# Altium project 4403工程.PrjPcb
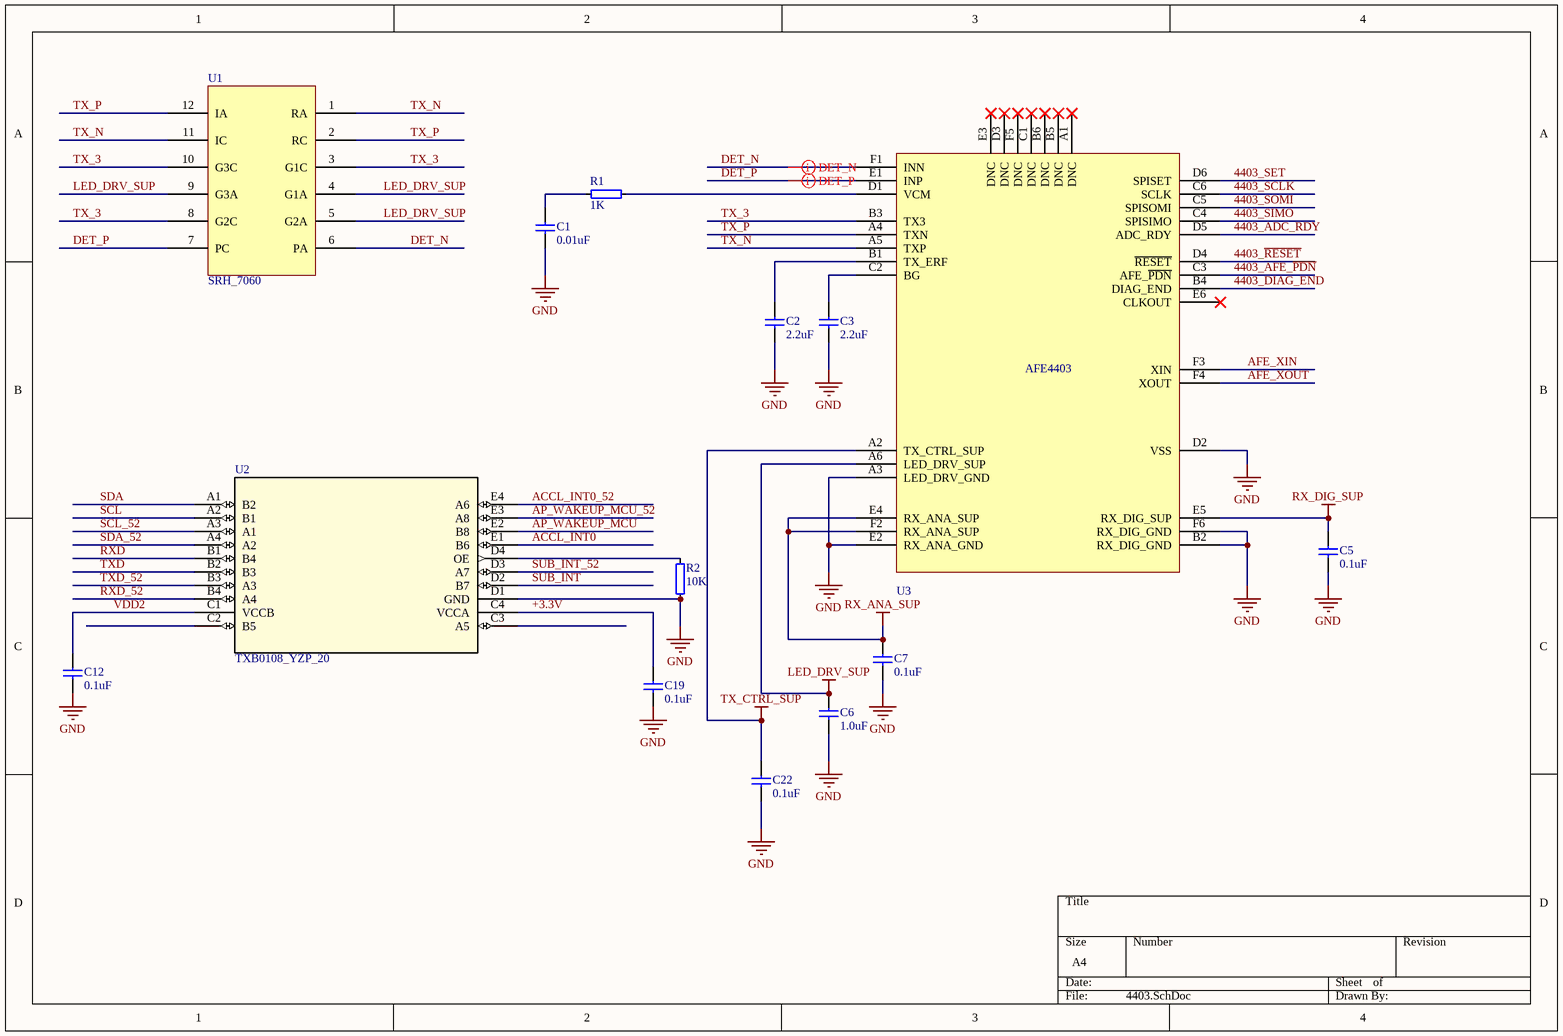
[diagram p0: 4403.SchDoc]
3 sheets, 38 parts. Net scope: global (net labels, ports and power ports of the same name join across sheets).
Board file: 4403_PCB.PcbDoc
Sheets:
  4403.SchDoc
  pca10040_sheet1_radio.SchDoc
  POWER.SchDoc

## Sheet 4403.SchDoc
size A4

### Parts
C1  0.01uF  [0201]
C2  2.2uF  [0402]
C3  2.2uF  [0402]
C5  0.1uF  [0201]
C6  1.0uF  [0402]
C7  0.1uF  [0201]
C12  0.1uF  [0201]
C19  0.1uF  [0201]
C22  0.1uF  [0201]
R1  1K  [0201]
R2  10K  [0201]
U1  SRH_7060  [SRH_7060]
U2  TXB0108_YZP_20  [BGA20C50P4X5_189X239X50]
U3  AFE4403  [BGA36C50P6X6_304X304X50]

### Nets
+3.3V: C5.2 C7.2 C19.2 U2.C4(VCCA) U3.E4(RX_ANA_SUP) U3.E5(RX_DIG_SUP) U3.F2(RX_ANA_SUP)  [also labelled RX_ANA_SUP, RX_DIG_SUP]
GND: C1.1 C2.1 C3.1 C5.1 C6.1 C7.1 C12.1 C19.1 C22.1 R2.1 U2.D1(GND) U3.A3(LED_DRV_GND) U3.B2(RX_DIG_GND) U3.D2(VSS) U3.E2(RX_ANA_GND) U3.F6(RX_DIG_GND)
LED_DRV_SUP: C6.2 C22.2 U1.4(G1A) U1.5(G2A) U1.9(G3A) U3.A2(TX_CTRL_SUP) U3.A6(LED_DRV_SUP)  [also labelled TX_CTRL_SUP]
4403_ADC_RDY: U3.D5(ADC_RDY)
4403_AFE_~{PDN}: U3.C3(AFE_~{PDN})
4403_DIAG_END: U3.B4(DIAG_END)
4403_~{RESET}: U3.D4(~{RESET})
4403_SCLK: U3.C6(SCLK)
4403_SET: U3.D6(SPISET)
4403_SIMO: U3.C4(SPISIMO)
4403_SOMI: U3.C5(SPISOMI)
ACCL_INT0: U2.E1(B6)
ACCL_INT0_52: U2.E4(A6)
AFE_XIN: U3.F3(XIN)
AFE_XOUT: U3.F4(XOUT)
AP_WAKEUP_MCU: U2.E2(B8)
AP_WAKEUP_MCU_52: U2.E3(A8)
DET_N: U1.6(PA) U3.F1(INN)
DET_P: U1.7(PC) U3.E1(INP)
RXD: U2.B1(B4)
RXD_52: U2.B4(A4)
SCL: U2.A2(B1)
SCL_52: U2.A3(A1)
SDA: U2.A1(B2)
SDA_52: U2.A4(A2)
SUB_INT: U2.D2(B7)
SUB_INT_52: U2.D3(A7)
TX_3: U1.3(G1C) U1.8(G2C) U1.10(G3C) U3.B3(TX3)
TX_N: U1.1(RA) U1.11(IC) U3.A5(TXP)
TX_P: U1.2(RC) U1.12(IA) U3.A4(TXN)
TXD: U2.B2(B3)
TXD_52: U2.B3(A3)
VDD2: C12.2 U2.C1(VCCB)
NetC1_2: C1.2 R1.1
NetC2_2: C2.2 U3.B1(TX_ERF)
NetC3_2: C3.2 U3.C2(BG)
NetR1_2: R1.2 U3.D1(VCM)
NetR2_2: R2.2 U2.D4(OE)

Not connected (* = marked no-connect by the designer): U2 C2(B5) C3(A5); U3 A1(DNC)* B5(DNC)* B6(DNC)* C1(DNC)* D3(DNC)* E3(DNC)* E6(CLKOUT)* F5(DNC)*

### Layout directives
differential pair: DET_N, DET_P

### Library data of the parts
C1 C5 C7 C12 C19 C22 = CAP_0201: Capacitor, NP0, ±0.1pF; Part Number: C0201-1.2p; Note: 50V; Artikkelnr Noca: 20029157; Artikkelnr Simpro: N.A.
C2 C3 C6 = CAP_0402: Capacitor, NP0, ±0.1pF; Part Number: C0402-1.2p; Note: 50V; Artikkelnr Noca: 20029157; Artikkelnr Simpro: N.A.
R1 R2 = RES_0201: Not mounted; Part Number: R0201-N.C.; Note: Chip Res; Artikkelnr Noca: N.A.
U2 = TXB0108_YZP_20: Imported; Vendor: Texas Instruments; PACKAGE_DESIGNATOR: YZP; PIN_COUNT: 20; FAMILY_NAME: AUTO DIRECTION SENSING DUAL SUPPLY TRANSLATOR; INDUSTRY_STD_PKG_TYPE: DSBGA

## Sheet pca10040_sheet1_radio.SchDoc: PCA10040 - nRF Radio
size A4; Revision: 1.1.0; SheetNumber: 1; SheetTotal: 5; DrawnBy: KJP; ProjectNumber: 4397; PCBRevision: 0071KJP; DocumentSize: A4; PCAName: PCA10040; PCBNumber: 400150
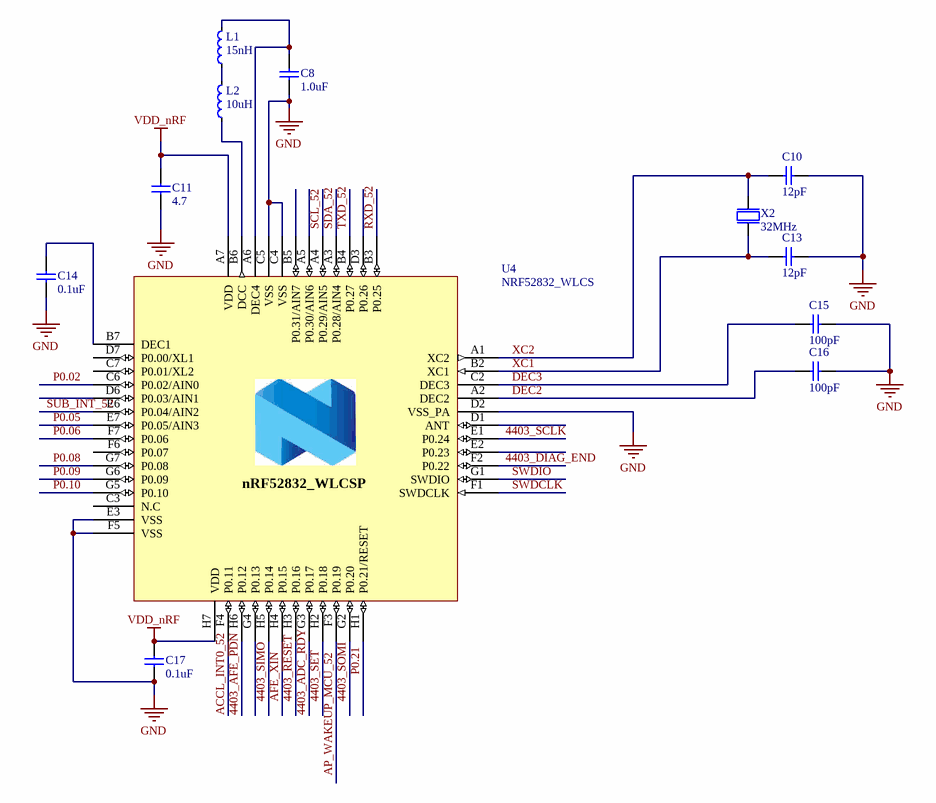
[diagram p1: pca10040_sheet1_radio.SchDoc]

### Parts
C8  1.0uF  [0402]
C10  12pF  [0201]
C11  4.7  [0603]
C13  12pF  [0201]
C14  0.1uF  [0201]
C15  100pF  [0201]
C16  100pF  [0201]
C17  0.1uF  [0201]
L1  15nH  [INDC1608X06L]
L2  10uH  [INDC1608X06L]
U4  NRF52832_WLCS  [BGA56C40P7X8_300X320X38]
X2  32MHz  [BT-XTAL_2016]

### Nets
GND: C8.1 C10.1 C11.1 C13.1 C14.1 C15.1 C16.1 C17.1 U4.C4(VSS) U4.C5(VSS) U4.D2(VSS_PA) U4.E3(VSS) U4.F5(VSS) X2.2(GND) X2.4(GND)
VDD_nRF: C11.2 C17.2 U4.A7(VDD) U4.H7(VDD)  [project net +3.3V]
4403_ADC_RDY: U4.G3(P0.17)
4403_AFE_~{PDN}: U4.H6(P0.12)
4403_DIAG_END: U4.F2(P0.22)
4403_~{RESET}: U4.H3(P0.16)
4403_SCLK: U4.E1(P0.24)
4403_SET: U4.H2(P0.18)
4403_SIMO: U4.H5(P0.14)
4403_SOMI: U4.G2(P0.20)
ACCL_INT0_52: U4.F4(P0.11)
AFE_XIN: U4.H4(P0.15)
AP_WAKEUP_MCU_52: U4.F3(P0.19)
DEC2: C16.2 U4.A2(DEC2)
DEC3: C15.2 U4.C2(DEC3)
P0.02: U4.C6(P0.02/AIN0)
P0.05: U4.E7(P0.05/AIN3)
P0.06: U4.F7(P0.06)
P0.08: U4.G7(P0.08)
P0.09: U4.G6(P0.09)
P0.10: U4.G5(P0.10)
P0.21: U4.H1(P0.21/RESET)
RXD_52: U4.B3(P0.25)
SCL_52: U4.A4(P0.29/AIN5)
SDA_52: U4.A3(P0.28/AIN4)
SUB_INT_52: U4.E6(P0.04/AIN2)
SWDCLK: U4.F1(SWDCLK)
SWDIO: U4.G1(SWDIO)
TXD_52: U4.B4(P0.27)
XC1: C13.2 U4.B2(XC1) X2.1(inp)
XC2: C10.2 U4.A1(XC2) X2.3(out)
NetC8_2: C8.2 L1.2 U4.A6(DEC4)
NetC14_2: C14.2 U4.B7(DEC1)
NetL1_1: L1.1 L2.2
NetL2_1: L2.1 U4.B6(DCC)

Not connected (* = marked no-connect by the designer): U4 A5(P0.30/AIN6) B5(P0.31/AIN7) C3(N.C) C7(P0.01/XL2) D1(ANT) D3(P0.26) D6(P0.03/AIN1) D7(P0.00/XL1) E2(P0.23) F6(P0.07) G4(P0.13)

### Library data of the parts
C8 = CAP_0402: as C2 on sheet 4403
C10 C13-C17 = CAP_0201: as C1 on sheet 4403
C11 = CAP_0603: Capacitor, NP0, ±0.1pF; Part Number: C0603-1.2p; Note: 50V; Artikkelnr Noca: 20029157; Artikkelnr Simpro: N.A.
L1 L2 = IND_0603: Inductor, 80mA, ±10%; Part Number: L0603-10µ; Manufacturer: Taiyo Yuden; Manufacturer Part Number: LBMF1608T100K; 2nd source part number: 178-6105; Note: LBMF1608T100K 10µH 80mA 0603; Artikkelnr Noca: 33029314; Artikkelnr Simpro: N.A.
U4 = NRF52832_WLCSP
X2 = XTAL_SMD2016: XTAL SMD 2016, 32MHz, Cl=8pF, Tol: ±10ppm, Stab: ±10ppm; Part Number: XTAL_SMD2016_32MHz_8pF_Epson; Manufacturer: Epson Toyocom; Manufacturer Part Number: Q22FA12800025; Note: XTAL SMD 32.000MHz; Artikkelnr Noca: N.A.

## Sheet POWER.SchDoc
size A4
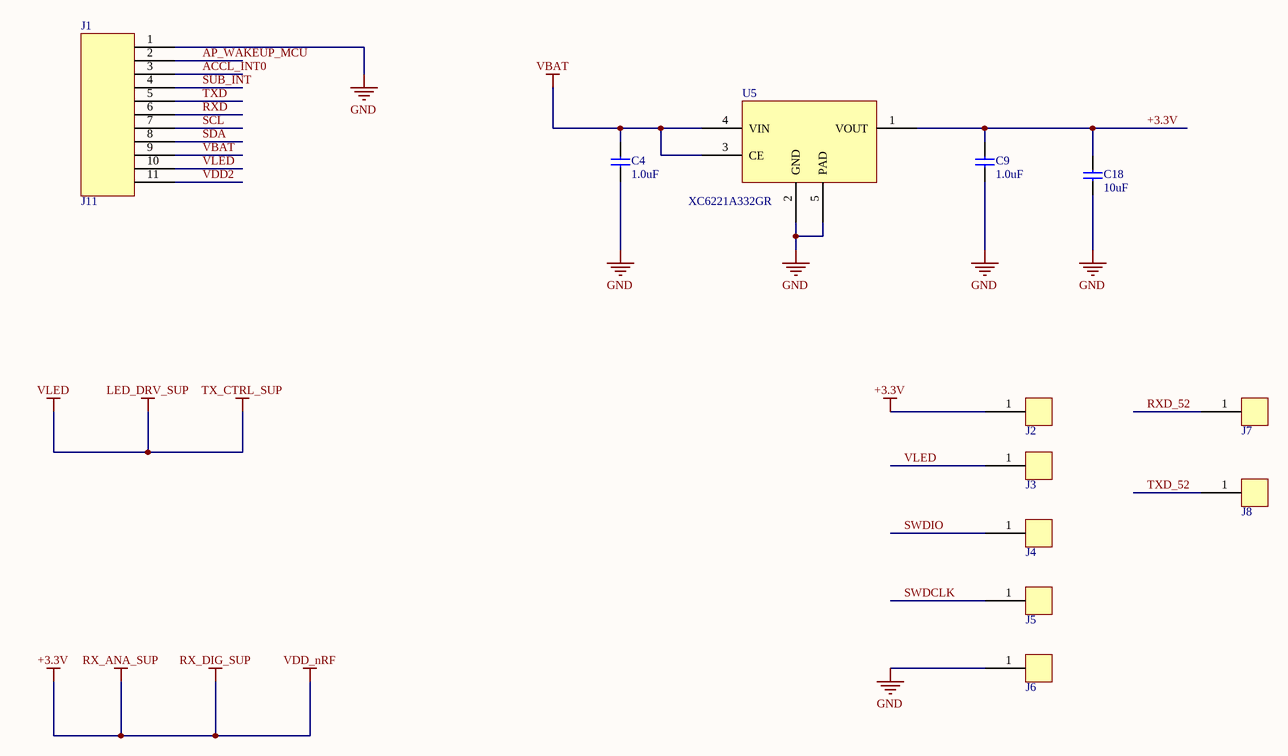
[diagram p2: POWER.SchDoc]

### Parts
C4  1.0uF  [0402]
C9  1.0uF  [0402]
C18  10uF  [0603]
J1  J11  [J11]
J2  PAD  [PAD1.5]  (value not drawn)
J3  PAD  [PAD1.5]  (value not drawn)
J4  PAD  [PAD1.5]  (value not drawn)
J5  PAD  [PAD1.5]  (value not drawn)
J6  PAD  [PAD1.5]  (value not drawn)
J7  PAD  [PAD1.5]  (value not drawn)
J8  PAD  [PAD1.5]  (value not drawn)
U5  XC6221A332GR  [USP-4]

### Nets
+3.3V: C9.2 C18.2 J2.1(PAD) U5.1(VOUT)  [also labelled RX_ANA_SUP, RX_DIG_SUP, VDD_nRF]
GND: C4.1 C9.1 C18.1 J1.1 J6.1(PAD) U5.2(GND) U5.5(PAD)
LED_DRV_SUP: J1.10 J3.1(PAD)  [also labelled TX_CTRL_SUP, VLED]
VBAT: C4.2 J1.9 U5.3(CE) U5.4(VIN)
ACCL_INT0: J1.3
AP_WAKEUP_MCU: J1.2
RXD: J1.6
RXD_52: J7.1(PAD)
SCL: J1.7
SDA: J1.8
SUB_INT: J1.4
SWDCLK: J5.1(PAD)
SWDIO: J4.1(PAD)
TXD: J1.5
TXD_52: J8.1(PAD)
VDD2: J1.11

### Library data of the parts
C4 C9 = CAP_0402: as C2 on sheet 4403
C18 = CAP_0603: as C11 on sheet pca10040_sheet1_radio

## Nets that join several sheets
+3.3V: 4403 (7 pins), pca10040_sheet1_radio (C11.2 C17.2 U4.A7 U4.H7), POWER (C9.2 C18.2 J2.1 U5.1)
GND: 4403 (16 pins), pca10040_sheet1_radio (15 pins), POWER (7 pins)
LED_DRV_SUP: 4403 (7 pins), POWER (J1.10 J3.1)
4403_ADC_RDY: 4403 (U3.D5), pca10040_sheet1_radio (U4.G3)
4403_AFE_~{PDN}: 4403 (U3.C3), pca10040_sheet1_radio (U4.H6)
4403_DIAG_END: 4403 (U3.B4), pca10040_sheet1_radio (U4.F2)
4403_~{RESET}: 4403 (U3.D4), pca10040_sheet1_radio (U4.H3)
4403_SCLK: 4403 (U3.C6), pca10040_sheet1_radio (U4.E1)
4403_SET: 4403 (U3.D6), pca10040_sheet1_radio (U4.H2)
4403_SIMO: 4403 (U3.C4), pca10040_sheet1_radio (U4.H5)
4403_SOMI: 4403 (U3.C5), pca10040_sheet1_radio (U4.G2)
ACCL_INT0: 4403 (U2.E1), POWER (J1.3)
ACCL_INT0_52: 4403 (U2.E4), pca10040_sheet1_radio (U4.F4)
AFE_XIN: 4403 (U3.F3), pca10040_sheet1_radio (U4.H4)
AP_WAKEUP_MCU: 4403 (U2.E2), POWER (J1.2)
AP_WAKEUP_MCU_52: 4403 (U2.E3), pca10040_sheet1_radio (U4.F3)
RXD: 4403 (U2.B1), POWER (J1.6)
RXD_52: 4403 (U2.B4), pca10040_sheet1_radio (U4.B3), POWER (J7.1)
SCL: 4403 (U2.A2), POWER (J1.7)
SCL_52: 4403 (U2.A3), pca10040_sheet1_radio (U4.A4)
SDA: 4403 (U2.A1), POWER (J1.8)
SDA_52: 4403 (U2.A4), pca10040_sheet1_radio (U4.A3)
SUB_INT: 4403 (U2.D2), POWER (J1.4)
SUB_INT_52: 4403 (U2.D3), pca10040_sheet1_radio (U4.E6)
SWDCLK: pca10040_sheet1_radio (U4.F1), POWER (J5.1)
SWDIO: pca10040_sheet1_radio (U4.G1), POWER (J4.1)
TXD: 4403 (U2.B2), POWER (J1.5)
TXD_52: 4403 (U2.B3), pca10040_sheet1_radio (U4.B4), POWER (J8.1)
VDD2: 4403 (C12.2 U2.C1), POWER (J1.11)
